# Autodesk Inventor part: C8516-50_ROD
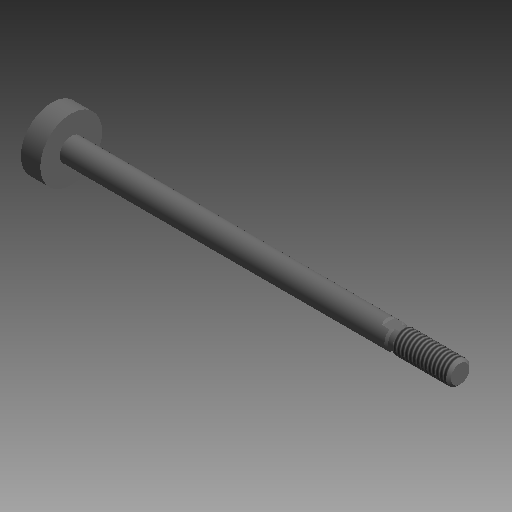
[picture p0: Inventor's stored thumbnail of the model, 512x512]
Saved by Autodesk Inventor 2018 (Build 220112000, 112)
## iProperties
Category: PARTsolutions
Company: SMC
Part Number: C8516-50_ROD
Material: Generic
Catalog Web Link: www.cadenas.de
Description: C85/CD85 ROD-ISO Standard Air Cylinder:Standard Type Double Acting Single Rod
Vendor: SMC
Document SubType Name: Modeling
Designer: partserver
Manufacturer: SMC
Mass: 3.82651 g
Surface Area: 25.4402 cm^2
Volume: 3.82651 cm^3
Density: 1 g/cm^3
Appearance: PSOLRGB-128-128-128
PSOL_IDENT_0: {$CADENAS_DATA\23d-libs\smc_jp\actuator\standard_air_cylinder\c85\c85\parts\c85_rod.prj},195 {VTYP=3
PSOL_IDENT_1: D},{NB=C8516-50_ROD},{LINA=C8516-50_ROD},{NN=C85/CD85 ROD},{DATE=09.12.2020 03:32:11},{GEOMDATE=26.0
PSOL_IDENT_2: 4.2020 02:54:00},{VERSION=},{LINEID=40},{WBVAR=STROKE,CUSHION,BOOT},{WBNUMERIC=STROKE}  {NB=C8516-50
PSOL_IDENT_3: _ROD},{LINA=C8516-50_ROD},{KT=DUMMY},{ORDER=C8516-50},{BORE=16},{STROKE=50},{CUSHION=},{BOOT=},{BOOT
PSOL_IDENT_4: X='','N/A' },{AM=16},{C=6},{F=17},{H=38},{K=5},{KK=M6x1},{KKD=6},{KKJ=1.00},{N1=12.5},{WH=0},{MAX=40
PSOL_IDENT_5: 0},{X1=5.300},{X2=3.500},{KW=5.0}
NB: C8516-50_ROD
NN: C85/CD85 ROD
NT: ISO Standard Air Cylinder:Standard Type Double Acting Single Rod
NBSYN: $ORDER._ROD
LINA: C8516-50_ROD
CATALOG: SMC (JP
BORE: 16
STROKE: 50
CUSHION: (-) Rubber bumper(Standard)
BOOT: N/A
AM: 16
C: 6
K: 5
KK: M6x1
KKD: 6
KKJ: 1
MAX: 400
X1: 5.3
X2: 3.5
KW: 5
SUPPLIER: SMC
ARTICLENO: C8516-50_ROD
BOMINFO: C8516-50_ROD
CREATOR: CADENAS GmbH
Title: C8516-50_ROD
Author: Cadenas PARTsolutions
Comments: ISO Standard Air Cylinder:Standard Type Double Acting Single Rod
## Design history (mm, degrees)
sketch "Sketch_1"
  geometry: L1 (67.5, 0)-(-38, 0); L2 (-38, 0)-(-38, 2.386); L3 (-38, 2.386)-(-37.386, 3); L4 (-37.386, 3)-(-23.5, 3); L5 (-23.5, 3)-(-23.5, 2.65); L6 (-23.5, 2.65)-(-22, 2.65); L7 (-22, 2.65)-(-21.394, 3); L8 (-21.394, 3)-(62.5, 3); L9 (62.5, 3)-(62.5, 8); L10 (62.5, 8)-(67.5, 8); L11 (67.5, 8)-(67.5, 0); L12 (67.5, 0)-(-38, 0)
  constraints: 24 end point
revolve "Revolution1" sketch "Sketch_1" stored, may be unused: angle "d0" = 360 deg
thread "Thread1" dims "d1" = 13.8865, "d2" = 0
sketch "Sketch_2"
  geometry: L1 (23.3, -7.5)-(23.3, -2.8); L2 (23.3, -2.8)-(23, -2.5); L3 (23, -2.5)-(19.5, -2.5); L4 (19.5, -2.5)-(14.5, -7.5); L5 (14.5, -7.5)-(23.3, -7.5)
  constraints: 10 end point
extrude "Extrusion1" cut sketch "Sketch_2" stored distance "d3" = 10; taper "d4" = 0 deg
sketch "Sketch_3"
  geometry: L1 (23.3, 7.5)-(14.5, 7.5); L2 (14.5, 7.5)-(19.5, 2.5); L3 (19.5, 2.5)-(23, 2.5); L4 (23, 2.5)-(23.3, 2.8); L5 (23.3, 2.8)-(23.3, 7.5)
  constraints: 10 end point
extrude "Extrusion2" cut sketch "Sketch_3" stored distance "d5" = 10; taper "d6" = 0 deg
node "ROD_BODY_XY"
node "ROD_BODY_YZ"
node "ROD_BODY_ZX"
node "ROD_BODY_X"
node "ROD_BODY_Y"
node "ROD_BODY_Z"
node "ROD_BODY_Center"
node "ROD_RODNUT_XY"
node "ROD_RODNUT_YZ"
node "ROD_RODNUT_ZX"
node "ROD_RODNUT_X"
node "ROD_RODNUT_Y"
node "ROD_RODNUT_Z"
node "ROD_RODNUT_Center"
node "Rod_Accessory_XY"
node "Rod_Accessory_YZ"
node "Rod_Accessory_ZX"
node "Rod_Accessory_X"
node "Rod_Accessory_Y"
node "Rod_Accessory_Z"
node "Rod_Accessory_Center"
body "Solid1"
